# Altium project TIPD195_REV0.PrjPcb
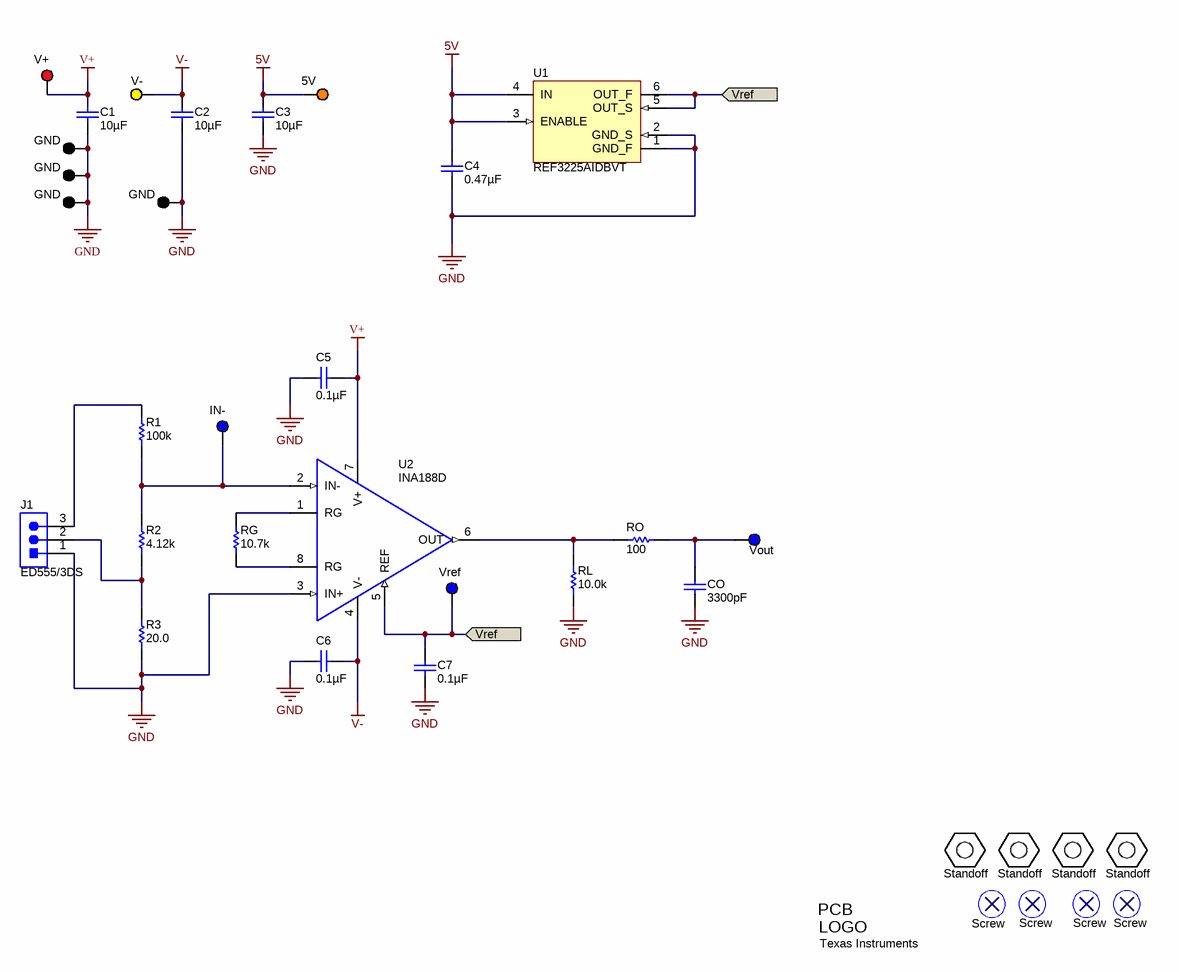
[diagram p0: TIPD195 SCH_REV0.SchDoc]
TechSupport: http://www.ti.com/support; SCH_Rev: A; PRJ_Title: 3 Terminal PLC Reference Design; PRJ_Customer: PA-Linear; CopyrightYear: 2015
1 sheet, 36 parts. Net scope: flat (ports and power ports of the same name join across sheets).
Board file: TIPD195 PCB_REV0.PcbDoc

## Sheet TIPD195 SCH_REV0.SchDoc: TIPD195 Schematic
size B; Date: Not shown in title block; ApprovedBy: Not shown in title block; CheckedBy: Not shown in title block; Author: Not shown in title block; CompanyName: Not shown in title block; DrawnBy: Not shown in title block; Engineer: Not shown in title block; Organization: Not shown in title block; Address1: Not shown in title block; Address2: Not shown in title block; Address3: Not shown in title block; Address4: Not shown in title block; DocumentNumber: 1; Revision: Use project parameter SCH_Rev; SheetNumber: 1; SheetTotal: 1; PageSetup: Record=PageOptions¦CenterHorizontal=True¦CenterVertical=True¦PrintScale=0.72¦XCorrection=1.00¦YCorrection=1.00¦PrintKind=0¦BorderSize=5000000¦LeftOffset=0¦BottomOffset=0¦Orientation=2¦PaperLength=1000¦PaperWidth=1000¦Scale=100¦PaperSource=15¦PrintQuality=600¦MediaType=1¦DitherType=10¦PaperKind=Letter¦PrintScaleMode=1

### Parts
C1  ValueDisplayed: 10µF  [0805_HV]  (hidden comment: GRM21BR6YA106KE43L)
C2  ValueDisplayed: 10µF  [0805_HV]  (hidden comment: GRM21BR6YA106KE43L)
C3  ValueDisplayed: 10µF  [0805_HV]  (hidden comment: GRM21BR6YA106KE43L)
C4  ValueDisplayed: 0.47µF  [0805_HV]  (hidden comment: TMK212BJ474KD-T)
C5  ValueDisplayed: 0.1µF  [0805_HV]  (hidden comment: 08055C104KAT2A)
C6  ValueDisplayed: 0.1µF  [0805_HV]  (hidden comment: 08055C104KAT2A)
C7  ValueDisplayed: 0.1µF  [0805_HV]  (hidden comment: 08055C104KAT2A)
CO  ValueDisplayed: 3300pF  [0805_HV]  (hidden comment: CC0805KRX7R9BB332)
J1  ED555/3DS  [TERM_BLK_ED555-3DS]
Logo1  Texas Instruments  [TI_Symbol_Overlay_Small]  (no BOM)
R1  ValueDisplayed: 100k  [0805_HV]  (hidden comment: RG2012P-104-B-T5)
R2  ValueDisplayed: 4.12k  [0805_HV]  (hidden comment: RT0805BRD074K12L)
R3  ValueDisplayed: 20.0  [0805_HV]  (hidden comment: RP73PF2A20RBTDF)
RG  ValueDisplayed: 10.7k  [0805_HV]  (hidden comment: RT0805BRD0710K7L)
RL  ValueDisplayed: 10.0k  [0805_HV]  (hidden comment: CRCW080510K0FKEA)
RO  ValueDisplayed: 100  [0805_HV]  (hidden comment: CRCW0805100RFKEA)
TP1  V+  [Keystone5005]
TP2  V-  [Keystone5009]
TP3  5V  [Keystone5008]
TP4  GND  [Keystone5006]
TP5  GND  [Keystone5006]
TP7  GND  [Keystone5006]
TP8  GND  [Keystone5006]
TP9  IN-  [Keystone5122]
TP10  Vout  [Keystone5122]
TP11  Vref  [Keystone5122]
U1  REF3225AIDBVT  [DBV0006A_N]
U2  INA188D  [D0008A_N]
U3  Standoff  [STANDOFF HEX 4-40THR ALUM 1"L]
U4  Standoff  [STANDOFF HEX 4-40THR ALUM 1"L]
U5  Standoff  [STANDOFF HEX 4-40THR ALUM 1"L]
U6  Standoff  [STANDOFF HEX 4-40THR ALUM 1"L]
U7  Screw  (mechanical)
U8  Screw  (mechanical)
U9  Screw  (mechanical)
U10  Screw  (mechanical)

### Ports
Vref

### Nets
5V: C3.1 C4.1 TP3.1 U1.3(ENABLE) U1.4(IN)
GND: C1.2 C2.2 C3.2 C4.2 C5.2 C6.1 C7.2 CO.2 J1.1 R3.1 RL.1 TP4.1 TP5.1 TP7.1 TP8.1 U1.1(GND_F) U1.2(GND_S) U2.3(IN+)
V+: C1.1 C5.1 TP1.1 U2.7(V+)
V-: C2.1 C6.2 TP2.1 U2.4(V-)
NetC7_1: C7.1 TP11.1 U1.5(OUT_S) U1.6(OUT_F) U2.5(REF) ; port Vref
NetCO_1: CO.1 RO.2 TP10.1
NetJ1_2: J1.2 R2.1 R3.2
NetJ1_3: J1.3 R1.2
NetR1_1: R1.1 R2.2 TP9.1 U2.2(IN-)
NetRG_1: RG.1 U2.8(RG)
NetRG_2: RG.2 U2.1(RG)
NetRL_2: RL.2 RO.1 U2.6(OUT)

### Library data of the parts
C1-C3 = GRM21BR6YA106KE43L: CAP, CERM, 10 µF, 35 V, +/- 10%, X5R, 0805; Manufacturer: MuRata; Polarized: N; CompType: Capacitor; Value: 10uF; U/M: EA; Cap_F: 0.00001; Tolerance_%: 10; Value1: Unknown; VDC_V: 35; Value2: 35V; TaMin_C: -55; TaMax_C: 85; Cap_Case: 0805
C4 = TMK212BJ474KD-T: CAP, CERM, 0.47 µF, 20 V, +/- 10%, X5R, 0805; Manufacturer: Taiyo Yuden; Polarized: N; CompType: Capacitor; Value: 0.47uF; U/M: EA; Cap_F: 0.00000047; Tolerance_%: 10; Value1: Unknown; VDC_V: 20; Value2: 20V; TaMin_C: -55; TaMax_C: 85; Cap_Case: 0805
C5-C7 = 08055C104KAT2A: CAP, CERM, 0.1 µF, 50 V, +/- 10%, X7R, 0805; Manufacturer: AVX; Polarized: N; CompType: Capacitor; Value: 0.1uF; U/M: EA; Cap_F: 0.0000001; Tolerance_%: 10; ESR_ohm: 0.024; Value1: 0.024 ohm; VDC_V: 50; Value2: 50V; TaMin_C: -55; TaMax_C: 125; Cap_Case: 0805
CO = CC0805KRX7R9BB332: CAP, CERM, 3300 pF, 50 V, +/- 10%, X7R, 0805; Manufacturer: Yageo America; Polarized: N; CompType: Capacitor; Value: 3300pF; U/M: EA; Cap_F: 0.0000000033; Tolerance_%: 10; Value1: Unknown; VDC_V: 50; Value2: 50V; TaMin_C: -55; TaMax_C: 125; Cap_Case: 0805
J1 = ED555/3DS: Terminal Block, 6A, 3.5mm Pitch, 3-Pos, TH; Manufacturer: On-Shore Technology; SymbolCreator: a0799628; CompType: Connector; U/M: EA
Logo1 = TI_Logo: Texas Instrument Corporate Signature; SymbolCreator: codlsc
R1 = RG2012P-104-B-T5: RES, 100 k, 0.1%, 0.125 W, 0805; Manufacturer: Susumu Co Ltd; CompType: Resistor; Value: 100k; Res_ohm: 100000; Tolerance_%: 0.1; Power_W: 0.125; Value2: 0.125W; VDC_V: 100; TempCo: 25 ppm/C; EIA_Code: E192; U/M: EA
R2 = RT0805BRD074K12L: RES, 4.12 k, 0.1%, 0.125 W, 0805; Manufacturer: Yageo America; CompType: Resistor; Value: 4.12k; Res_ohm: 4120; Value_Code: 4k12; Tolerance_%: 0.1; Power_W: 0.125; Value2: 0.125W; VDC_V: 150; TempCo: 25 ppm/C; EIA_Code: E192; U/M: EA
R3 = RP73PF2A20RBTDF: RES, 20.0, 0.1%, 0.25 W, 0805; Manufacturer: TE Connectivity; CompType: Resistor; Value: 20.0; Res_ohm: 20; Value_Code: 20R0; Tolerance_%: 0.1; Power_W: 0.25; Value2: 0.25W; VDC_V: 150; TempCo: 25 ppm/C; EIA_Code: E192; U/M: EA
RG = RT0805BRD0710K7L: RES, 10.7 k, 0.1%, 0.125 W, 0805; Manufacturer: Yageo America; CompType: Resistor; Value: 10.7k; Res_ohm: 10700; Value_Code: 10k7; Tolerance_%: 0.1; Power_W: 0.125; Value2: 0.125W; VDC_V: 150; TempCo: 25 ppm/C; EIA_Code: E192; U/M: EA
RL = CRCW080510K0FKEA: RES, 10.0 k, 1%, 0.125 W, 0805; Manufacturer: Vishay-Dale; CompType: Resistor; Value: 10.0k; Res_ohm: 10000; Value_Code: 10k0; Tolerance_%: 1; Power_W: 0.125; Value2: 0.125W; VDC_V: 150; TempCo: 100 ppm/C; EIA_Code: E96; U/M: EA
RO = CRCW0805100RFKEA: RES, 100, 1%, 0.125 W, 0805; Manufacturer: Vishay-Dale; CompType: Resistor; Value: 100; Value_Code: 100R; Tolerance_%: 1; Power_W: 0.125; Value2: 0.125W; VDC_V: 150; TempCo: 100 ppm/C; EIA_Code: E96; U/M: EA
TP1 = 5005: Test Point, TH, Compact, Red; Manufacturer: Keystone; Alternate Manufacturer: Any; Alternate PartNumber: Equivalent; CompType: Test Point Loop; U/M: EA
TP2 = 5009: Test Point, Compact, Yellow, TH; Manufacturer: Keystone; CompType: Test Point Loop; U/M: EA
TP3 = 5008: Test Point, Compact, Orange, TH; Manufacturer: Keystone; CompType: Test Point Loop; U/M: EA
TP4 TP5 TP7 TP8 = 5006: Test Point, TH, Compact, Black; Manufacturer: Keystone; Alternate Manufacturer: Any; Alternate PartNumber: Equivalent; CompType: Test Point Loop; U/M: EA
TP9-TP11 = 5122: Test Point, Compact, Blue, TH; Manufacturer: Keystone; CompType: Test Point Loop; U/M: EA
U1 = REF3225AIDBVT: 2.5 V, 4 ppm / degC, 100 uA Series (Bandgap) Voltage Reference, -40 to 125 degC, 6-pin SOT-23 (DBV), Green (RoHS & no Sb/Br); Manufacturer: Texas Instruments; Alternate Manufacturer: None; Alternate PartNumber: Equivalent; Initial Accuracy @ 25/deg C(%): 0.2; Iout/Iz(Max)(mA): 10; Iq(Max)(uA): 120; Rating: Catalog; SubFamily: Series Voltage Reference; Temp Coeff(Max)(ppm/ degree C): 7; Temp Coeff(Typ)(ppm/ degree C): 4; VI(Max)(V): 5.5; VI(Min)(V): 2.55; VO(V): 2.5
U2 = INA188D: INA188 Precision, Zero-Drift, Rail-to-Rail Out, High Voltage Instrumentation Amplifier, D0008A; Manufacturer: Texas Instruments; SymbolCreator: Altium; CompType: IC; U/M: EA
U3-U6 = Standoff, 1", 4-40, Alum, F-F: STANDOFF HEX 4-40THR ALUM 1"L; Manufacturer: Keystone; PartNumber: 2205; SymbolVersion: use current date i.e. 2008-05-20; SymbolCreator: Use LDAP id; CompType: Used in some BOM reports.  Useful for finding later.; U/M: EA, IN, or GM
U7-U10 = Machine Screw, 4-40, 0.25": MACHINE SCREW PAN PHILLIPS 4-40; Manufacturer: B&F Fastener Supply; PartNumber: PMSSS 440 0025 PH; SymbolVersion: use current date i.e. 2008-05-20; SymbolCreator: Use LDAP id; CompType: Mechanical; U/M: EA, IN, or GM

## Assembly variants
-100A: all parts fitted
